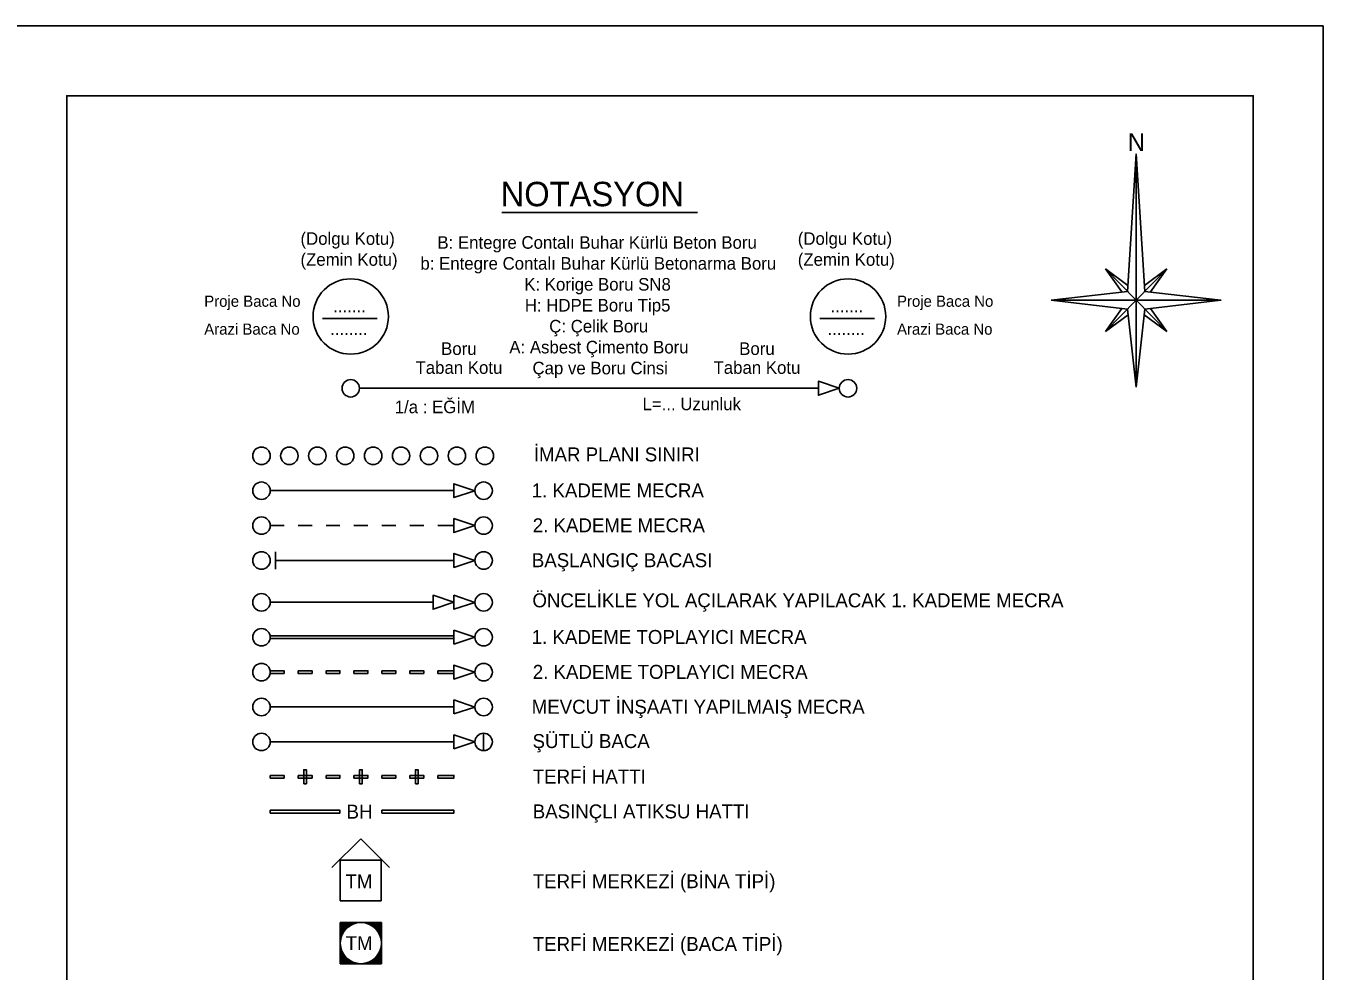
# Model space of a CAD drawing. Extents: x -10 to 821, y -10 to 550.
# Drawn here: x 635.2 to 821, y 414.6 to 550 of the extents above; entities that cross this region are included whole.
import ezdxf

# ---------------------------------------------------------------- set-up
doc = ezdxf.new("R2010")
doc.units = 0
for name, color, linetype in [('Default', 7, 'Continuous'), ('Lejand', 7, 'Continuous'), ('Level 51', 7, 'Continuous'), ('Level 52', 7, 'Continuous')]:
    doc.layers.add(name, color=color, linetype=linetype)

# ---------------------------------------------------------------- blocks, each defined once
blk = doc.blocks.new('OK')
at = {"layer": 'Default'}
blk.add_lwpolyline([(1.25, 0), (4.25, 1), (4.25, -1), (1.25, 0)], dxfattribs=at)
blk = doc.blocks.new('MENHOLE')
at = {"layer": 'Default'}
blk.add_circle((0, 0), 1.25, dxfattribs=at)

msp = doc.modelspace()

# ---------------------------------------------------------------- linework, layer by layer
at = {"layer": 'Lejand'}
for p, q in [((794.22, 531.67), (792.97, 511.96)), ((794.22, 531.67), (795.47, 511.96)), ((794.22, 531.67), (794.22, 498.23)), ((703.33, 523.26), (731.35, 523.26)), ((789.84, 515.17), (793.03, 512.81)), ((792.17, 511.87), (789.84, 515.17)), ((789.84, 515.17), (794.22, 510.68)), ((798.6, 515.17), (794.22, 510.68)), ((798.6, 515.17), (795.42, 512.81)), ((796.27, 511.87), (798.6, 515.17)), ((782.03, 510.68), (792.97, 511.96)), ((806.35, 510.68), (795.47, 511.96)), ((794.22, 510.68), (782.03, 510.68)), ((782.03, 510.68), (792.97, 509.4)), ((789.84, 506.19), (794.22, 510.68)), ((792.17, 509.49), (789.84, 506.19)), ((792.97, 509.4), (794.22, 498.23)), ((798.6, 506.19), (794.22, 510.68)), ((794.22, 510.68), (806.41, 510.68)), ((795.47, 509.4), (794.22, 498.23)), ((806.35, 510.68), (795.47, 509.4)), ((796.27, 509.49), (798.6, 506.19)), ((677.65, 508.07), (685.48, 508.07)), ((748.9, 508.07), (756.74, 508.07)), ((789.84, 506.19), (793.07, 508.58)), ((798.6, 506.19), (795.38, 508.58)), ((682.94, 498.07), (748.69, 498.08)), ((696.48, 483.4), (670.15, 483.4)), ((672.15, 478.4), (670.15, 478.4)), ((676.15, 478.4), (674.15, 478.4)), ((680.15, 478.4), (678.15, 478.4)), ((684.15, 478.4), (682.15, 478.4)), ((688.15, 478.4), (686.15, 478.4)), ((692.15, 478.4), (690.15, 478.4)), ((696.48, 478.4), (694.15, 478.4)), ((670.9, 474.64), (670.9, 472.14)), ((696.48, 473.4), (670.9, 473.4)), ((693.48, 467.41), (670.15, 467.41)), ((696.48, 452.4), (670.15, 452.4)), ((696.48, 447.4), (670.15, 447.4)), ((683.12, 433.5), (678.98, 429.37)), ((683.12, 433.5), (687.25, 429.37)), ((686.04, 430.45), (680.19, 430.45)), ((680.19, 430.45), (680.19, 424.6)), ((686.04, 430.45), (686.04, 424.6)), ((686.04, 424.6), (680.19, 424.6)), ((680.19, 421.5), (680.19, 415.6)), ((686.09, 421.5), (680.19, 421.5)), ((682.38, 421.4), (680.19, 421.4)), ((682.07, 421.3), (680.19, 421.3)), ((681.85, 421.2), (680.19, 421.2)), ((681.66, 421.1), (680.19, 421.1)), ((681.5, 421), (680.19, 421)), ((681.36, 420.9), (680.19, 420.9)), ((681.23, 420.8), (680.19, 420.8)), ((681.12, 420.7), (680.19, 420.7)), ((681.02, 420.6), (680.19, 420.6)), ((680.93, 420.5), (680.19, 420.5)), ((680.84, 420.4), (680.19, 420.4)), ((680.77, 420.3), (680.19, 420.3)), ((680.7, 420.2), (680.19, 420.2)), ((680.63, 420.1), (680.19, 420.1)), ((680.29, 421.5), (680.29, 419.31)), ((680.39, 421.5), (680.39, 419.62)), ((680.49, 421.5), (680.49, 419.85)), ((680.59, 421.5), (680.59, 420.03)), ((680.69, 421.5), (680.69, 420.19)), ((680.79, 421.5), (680.79, 420.33)), ((680.89, 421.5), (680.89, 420.46)), ((680.99, 421.5), (680.99, 420.57)), ((681.09, 421.5), (681.09, 420.67)), ((681.19, 421.5), (681.19, 420.76)), ((681.29, 421.5), (681.29, 420.85)), ((681.39, 421.5), (681.39, 420.93)), ((681.49, 421.5), (681.49, 421)), ((681.59, 421.5), (681.59, 421.06)), ((681.69, 421.5), (681.69, 421.12)), ((681.79, 421.5), (681.79, 421.17)), ((681.89, 421.5), (681.89, 421.22)), ((681.99, 421.5), (681.99, 421.27)), ((682.09, 421.5), (682.09, 421.31)), ((682.19, 421.5), (682.19, 421.34)), ((682.29, 421.5), (682.29, 421.38)), ((682.39, 421.5), (682.39, 421.4)), ((682.49, 421.5), (682.49, 421.43)), ((682.59, 421.5), (682.59, 421.45)), ((682.69, 421.5), (682.69, 421.47)), ((682.79, 421.5), (682.79, 421.48)), ((683.39, 421.5), (683.39, 421.49)), ((683.49, 421.5), (683.49, 421.48)), ((683.59, 421.5), (683.59, 421.47)), ((683.69, 421.5), (683.69, 421.45)), ((683.79, 421.5), (683.79, 421.43)), ((683.89, 421.5), (683.89, 421.4)), ((686.09, 421.4), (683.9, 421.4)), ((683.99, 421.5), (683.99, 421.38)), ((684.09, 421.5), (684.09, 421.34)), ((684.19, 421.5), (684.19, 421.31)), ((686.09, 421.3), (684.21, 421.3)), ((684.29, 421.5), (684.29, 421.27)), ((684.39, 421.5), (684.39, 421.22)), ((686.09, 421.2), (684.44, 421.2)), ((684.49, 421.5), (684.49, 421.17)), ((684.59, 421.5), (684.59, 421.12)), ((686.09, 421.1), (684.63, 421.1)), ((684.69, 421.5), (684.69, 421.06)), ((684.79, 421.5), (684.79, 421)), ((686.09, 421), (684.79, 421)), ((684.89, 421.5), (684.89, 420.93)), ((686.09, 420.9), (684.93, 420.9)), ((684.99, 421.5), (684.99, 420.85)), ((686.09, 420.8), (685.05, 420.8)), ((685.09, 421.5), (685.09, 420.76)), ((686.09, 420.7), (685.16, 420.7)), ((685.19, 421.5), (685.19, 420.67)), ((686.09, 420.6), (685.26, 420.6)), ((685.29, 421.5), (685.29, 420.57)), ((686.09, 420.5), (685.36, 420.5)), ((685.39, 421.5), (685.39, 420.46)), ((686.09, 420.4), (685.44, 420.4)), ((685.49, 421.5), (685.49, 420.33)), ((686.09, 420.3), (685.52, 420.3)), ((685.59, 421.5), (685.59, 420.19)), ((686.09, 420.2), (685.59, 420.2)), ((686.09, 420.1), (685.65, 420.1)), ((685.69, 421.5), (685.69, 420.03)), ((685.79, 421.5), (685.79, 419.85)), ((685.89, 421.5), (685.89, 419.62)), ((685.99, 421.5), (685.99, 419.31)), ((686.09, 421.5), (686.09, 415.6)), ((680.57, 420), (680.19, 420)), ((680.52, 419.9), (680.19, 419.9)), ((680.47, 419.8), (680.19, 419.8)), ((680.43, 419.7), (680.19, 419.7)), ((680.39, 419.6), (680.19, 419.6)), ((680.35, 419.5), (680.19, 419.5)), ((680.32, 419.4), (680.19, 419.4)), ((680.29, 419.3), (680.19, 419.3)), ((680.26, 419.2), (680.19, 419.2)), ((680.24, 419.1), (680.19, 419.1)), ((680.23, 419), (680.19, 419)), ((680.21, 418.9), (680.19, 418.9)), ((680.2, 418.8), (680.19, 418.8)), ((680.2, 418.4), (680.19, 418.4)), ((680.21, 418.2), (680.19, 418.2)), ((686.09, 420), (685.71, 420)), ((686.09, 419.9), (685.77, 419.9)), ((686.09, 419.8), (685.81, 419.8)), ((686.09, 419.7), (685.86, 419.7)), ((686.09, 419.6), (685.9, 419.6)), ((686.09, 419.5), (685.94, 419.5)), ((686.09, 419.4), (685.97, 419.4)), ((686.09, 419.3), (686, 419.3)), ((686.09, 419.2), (686.02, 419.2)), ((686.09, 419.1), (686.04, 419.1)), ((686.09, 419), (686.06, 419)), ((686.09, 418.9), (686.07, 418.9)), ((686.09, 418.2), (686.07, 418.2)), ((686.09, 418.3), (686.08, 418.3)), ((680.23, 418.1), (680.19, 418.1)), ((680.24, 418), (680.19, 418)), ((680.26, 417.9), (680.19, 417.9)), ((680.29, 417.8), (680.19, 417.8)), ((680.32, 417.7), (680.19, 417.7)), ((680.35, 417.6), (680.19, 417.6)), ((680.39, 417.5), (680.19, 417.5)), ((680.43, 417.4), (680.19, 417.4)), ((680.47, 417.3), (680.19, 417.3)), ((680.52, 417.2), (680.19, 417.2)), ((680.57, 417.1), (680.19, 417.1)), ((680.63, 417), (680.19, 417)), ((680.7, 416.9), (680.19, 416.9)), ((680.77, 416.8), (680.19, 416.8)), ((680.84, 416.7), (680.19, 416.7)), ((680.93, 416.6), (680.19, 416.6)), ((681.02, 416.5), (680.19, 416.5)), ((681.12, 416.4), (680.19, 416.4)), ((681.23, 416.3), (680.19, 416.3)), ((680.29, 417.79), (680.29, 415.6)), ((680.39, 417.48), (680.39, 415.6)), ((680.49, 417.25), (680.49, 415.6)), ((680.59, 417.07), (680.59, 415.6)), ((680.69, 416.91), (680.69, 415.6)), ((680.79, 416.77), (680.79, 415.6)), ((680.89, 416.64), (680.89, 415.6)), ((680.99, 416.53), (680.99, 415.6)), ((681.09, 416.43), (681.09, 415.6)), ((681.19, 416.34), (681.19, 415.6)), ((686.09, 416.3), (685.05, 416.3)), ((685.09, 416.34), (685.09, 415.6)), ((686.09, 416.4), (685.16, 416.4)), ((685.19, 416.43), (685.19, 415.6)), ((686.09, 416.5), (685.26, 416.5)), ((685.29, 416.53), (685.29, 415.6)), ((686.09, 416.6), (685.36, 416.6)), ((685.39, 416.64), (685.39, 415.6)), ((686.09, 416.7), (685.44, 416.7)), ((685.49, 416.77), (685.49, 415.6)), ((686.09, 416.8), (685.52, 416.8)), ((685.59, 416.91), (685.59, 415.6)), ((686.09, 416.9), (685.59, 416.9)), ((686.09, 417), (685.65, 417)), ((685.69, 417.07), (685.69, 415.6)), ((686.09, 417.1), (685.71, 417.1)), ((686.09, 417.2), (685.77, 417.2)), ((685.79, 417.25), (685.79, 415.6)), ((686.09, 417.3), (685.81, 417.3)), ((686.09, 417.4), (685.86, 417.4)), ((685.89, 417.48), (685.89, 415.6)), ((686.09, 417.5), (685.9, 417.5)), ((686.09, 417.6), (685.94, 417.6)), ((686.09, 417.7), (685.97, 417.7)), ((685.99, 417.79), (685.99, 415.6)), ((686.09, 417.8), (686, 417.8)), ((686.09, 417.9), (686.02, 417.9)), ((686.09, 418), (686.04, 418)), ((686.09, 418.1), (686.06, 418.1)), ((681.36, 416.2), (680.19, 416.2)), ((681.5, 416.1), (680.19, 416.1)), ((681.66, 416), (680.19, 416)), ((681.85, 415.9), (680.19, 415.9)), ((682.07, 415.8), (680.19, 415.8)), ((682.38, 415.7), (680.19, 415.7)), ((686.09, 415.6), (680.19, 415.6)), ((681.29, 416.25), (681.29, 415.6)), ((681.39, 416.18), (681.39, 415.6)), ((681.49, 416.1), (681.49, 415.6)), ((681.59, 416.04), (681.59, 415.6)), ((681.69, 415.98), (681.69, 415.6)), ((681.79, 415.93), (681.79, 415.6)), ((681.89, 415.88), (681.89, 415.6)), ((681.99, 415.83), (681.99, 415.6)), ((682.09, 415.79), (682.09, 415.6)), ((682.19, 415.76), (682.19, 415.6)), ((682.29, 415.73), (682.29, 415.6)), ((682.39, 415.7), (682.39, 415.6)), ((682.49, 415.67), (682.49, 415.6)), ((682.59, 415.65), (682.59, 415.6)), ((682.69, 415.63), (682.69, 415.6)), ((682.79, 415.62), (682.79, 415.6)), ((683.49, 415.62), (683.49, 415.6)), ((683.59, 415.63), (683.59, 415.6)), ((683.69, 415.65), (683.69, 415.6)), ((683.79, 415.67), (683.79, 415.6)), ((683.89, 415.7), (683.89, 415.6)), ((686.09, 415.7), (683.9, 415.7)), ((683.99, 415.73), (683.99, 415.6)), ((684.09, 415.76), (684.09, 415.6)), ((684.19, 415.79), (684.19, 415.6)), ((686.09, 415.8), (684.21, 415.8)), ((684.29, 415.83), (684.29, 415.6)), ((684.39, 415.88), (684.39, 415.6)), ((686.09, 415.9), (684.44, 415.9)), ((684.49, 415.93), (684.49, 415.6)), ((684.59, 415.98), (684.59, 415.6)), ((686.09, 416), (684.63, 416)), ((684.69, 416.04), (684.69, 415.6)), ((684.79, 416.1), (684.79, 415.6)), ((686.09, 416.1), (684.79, 416.1)), ((684.89, 416.18), (684.89, 415.6)), ((686.09, 416.2), (684.93, 416.2)), ((684.99, 416.25), (684.99, 415.6))]:
    msp.add_line(p, q, dxfattribs=at)
for points in [[(670.15, 462.6), (696.48, 462.6), (696.48, 462.2), (670.15, 462.2)], [(670.15, 457.6), (672.15, 457.6), (672.15, 457.2), (670.15, 457.2)], [(674.15, 457.6), (676.15, 457.6), (676.15, 457.2), (674.15, 457.2)], [(678.15, 457.6), (680.15, 457.6), (680.15, 457.2), (678.15, 457.2)], [(682.15, 457.6), (684.15, 457.6), (684.15, 457.2), (682.15, 457.2)], [(686.15, 457.6), (688.15, 457.6), (688.15, 457.2), (686.15, 457.2)], [(690.15, 457.6), (692.15, 457.6), (692.15, 457.2), (690.15, 457.2)], [(694.15, 457.6), (696.48, 457.6), (696.48, 457.2), (694.15, 457.2)], [(696.47, 451.4), (696.48, 453.4), (699.48, 452.39)], [(670.15, 442.6), (672.15, 442.6), (672.15, 442.2), (670.15, 442.2)], [(674.15, 442.6), (676.15, 442.6), (676.15, 442.2), (674.15, 442.2)], [(674.95, 441.4), (674.95, 443.4), (675.35, 443.4), (675.35, 441.4)], [(678.15, 442.6), (680.15, 442.6), (680.15, 442.2), (678.15, 442.2)], [(682.15, 442.6), (684.15, 442.6), (684.15, 442.2), (682.15, 442.2)], [(682.95, 441.4), (682.95, 443.4), (683.35, 443.4), (683.35, 441.4)], [(686.15, 442.6), (688.15, 442.6), (688.15, 442.2), (686.15, 442.2)], [(690.15, 442.6), (692.15, 442.6), (692.15, 442.2), (690.15, 442.2)], [(690.95, 441.4), (690.95, 443.4), (691.35, 443.4), (691.35, 441.4)], [(694.15, 442.6), (696.48, 442.6), (696.48, 442.2), (694.15, 442.2)], [(670.15, 437.6), (680.15, 437.6), (680.15, 437.2), (670.15, 437.2)], [(686.15, 437.6), (696.48, 437.6), (696.48, 437.2), (686.15, 437.2)]]:
    msp.add_lwpolyline(points, close=True, dxfattribs=at)
msp.add_lwpolyline([(700.73, 446.14), (700.97, 446.16), (701.21, 446.23), (701.42, 446.35), (701.61, 446.51), (701.77, 446.7), (701.88, 446.91), (701.95, 447.15), (701.98, 447.39), (701.95, 447.63), (701.88, 447.87), (701.77, 448.08), (701.61, 448.27), (701.42, 448.43), (701.21, 448.54), (700.97, 448.62), (700.73, 448.64), (700.73, 446.14)], dxfattribs=at)
for centre, radius in [((681.69, 508.36), 5.4), ((752.94, 508.36), 5.4), ((668.9, 488.39), 1.25), ((672.9, 488.39), 1.25), ((676.9, 488.39), 1.25), ((680.9, 488.39), 1.25), ((684.9, 488.39), 1.25), ((688.9, 488.39), 1.25), ((692.9, 488.39), 1.25), ((696.9, 488.39), 1.25), ((700.9, 488.39), 1.25), ((668.9, 452.39), 1.25), ((700.73, 452.39), 1.25), ((683.14, 418.55), 2.95)]:
    msp.add_circle(centre, radius, dxfattribs=at)
at = {"layer": 'Level 51'}
msp.add_lwpolyline([(-10, -10), (821, -10), (821, 550), (-10, 550)], close=True, dxfattribs=at)
at = {"layer": 'Level 52'}
msp.add_lwpolyline([(641, 287), (811, 287), (811, 540), (641, 540)], close=True, dxfattribs=at)

# ---------------------------------------------------------------- block references
at = {"layer": 'Lejand'}
for name, p, xscale, yscale, rotation in [('MENHOLE', (681.69, 498.07), 1.0000122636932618, 1.0000122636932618, 0.0008205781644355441), ('OK', (752.94, 498.07), 1.000012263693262, 1.0000122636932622, 179.87420678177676), ('MENHOLE', (752.94, 498.07), 1.0000122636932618, 1.0000122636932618, 0.0008205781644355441), ('MENHOLE', (668.9, 483.39), 1.0000122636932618, 1.0000122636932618, 0.0008205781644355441), ('OK', (700.73, 483.39), 1.000012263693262, 1.0000122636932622, 179.87420678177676), ('MENHOLE', (700.73, 483.39), 1.0000122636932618, 1.0000122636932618, 0.0008205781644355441), ('MENHOLE', (668.9, 478.39), 1.0000122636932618, 1.0000122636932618, 0.0008205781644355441), ('MENHOLE', (700.73, 478.39), 1.0000122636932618, 1.0000122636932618, 0.0008205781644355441), ('OK', (700.73, 478.39), 1.000012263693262, 1.0000122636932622, 179.87420678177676), ('MENHOLE', (668.9, 473.39), 1.0000122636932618, 1.0000122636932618, 0.0008205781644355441), ('OK', (700.73, 473.39), 1.000012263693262, 1.0000122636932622, 179.87420678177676), ('MENHOLE', (700.73, 473.39), 1.0000122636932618, 1.0000122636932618, 0.0008205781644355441), ('MENHOLE', (668.9, 467.39), 1.0000122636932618, 1.0000122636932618, 0.0008205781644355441), ('OK', (697.73, 467.4), 1.000012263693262, 1.0000122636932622, 179.87420678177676), ('OK', (700.73, 467.39), 1.000012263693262, 1.0000122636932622, 179.87420678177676), ('MENHOLE', (700.73, 467.39), 1.0000122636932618, 1.0000122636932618, 0.0008205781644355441), ('MENHOLE', (668.9, 462.39), 1.0000122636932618, 1.0000122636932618, 0.0008205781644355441), ('OK', (700.73, 462.39), 1.000012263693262, 1.0000122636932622, 179.87420678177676), ('MENHOLE', (700.73, 462.39), 1.0000122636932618, 1.0000122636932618, 0.0008205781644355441), ('MENHOLE', (668.9, 457.39), 1.0000122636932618, 1.0000122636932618, 0.0008205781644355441), ('OK', (700.73, 457.39), 1.000012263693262, 1.0000122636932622, 179.87420678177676), ('MENHOLE', (700.73, 457.39), 1.0000122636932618, 1.0000122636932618, 0.0008205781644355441), ('MENHOLE', (668.9, 447.39), 1.0000122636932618, 1.0000122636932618, 0.0008205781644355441), ('OK', (700.73, 447.39), 1.000012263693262, 1.0000122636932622, 179.87420678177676), ('MENHOLE', (700.73, 447.39), 1.0000122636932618, 1.0000122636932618, 0.0008205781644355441)]:
    msp.add_blockref(name, p, dxfattribs=dict(at, xscale=xscale, yscale=yscale, rotation=rotation))

# ---------------------------------------------------------------- texts
msp.add_text('N', height=2.56, dxfattribs=at).set_placement((793.02, 532.06))
for s, height, p in [('NOTASYON', 3.5, (703.17, 524.16)), ('(Dolgu Kotu)', 1.8, (674.49, 518.63)), ('(Dolgu Kotu)', 1.8, (745.74, 518.63)), ('B: Entegre Contalı Buhar Kürlü Beton Boru', 1.8, (694.11, 518.07)), ('(Zemin Kotu)', 1.8, (674.49, 515.63)), ('b: Entegre Contalı Buhar Kürlü Betonarma Boru', 1.8, (691.67, 515.07)), ('(Zemin Kotu)', 1.8, (745.74, 515.63)), ('K: Korige Boru SN8', 1.8, (706.55, 512.07)), ('Proje Baca No', 1.6, (660.7, 509.75)), ('Proje Baca No', 1.6, (759.96, 509.75)), ('.......', 1.8, (679.16, 508.94)), ('H: HDPE Boru Tip5', 1.8, (706.63, 509.07)), ('.......', 1.8, (750.41, 508.94)), ('Arazi Baca No', 1.6, (660.7, 505.75)), ('Ç: Çelik Boru', 1.8, (710.13, 506.07)), ('Arazi Baca No', 1.6, (759.96, 505.75)), ('........', 1.8, (678.75, 505.7)), ('........', 1.8, (750, 505.7)), ('Boru', 1.8, (694.64, 502.85)), ('A: Asbest Çimento Boru', 1.8, (704.41, 503.07)), ('Boru', 1.8, (737.35, 502.85)), ('Taban Kotu', 1.8, (690.97, 500.14)), ('Çap ve Boru Cinsi', 1.8, (707.73, 500.07)), ('Taban Kotu', 1.8, (733.67, 500.14)), ('1/a : EĞİM', 1.8, (687.99, 494.5)), ('L=... Uzunluk', 1.8, (723.49, 494.93)), ('İMAR PLANI SINIRI', 2, (707.92, 487.59)), ('1. KADEME MECRA', 2, (707.62, 482.43)), ('2. KADEME MECRA', 2, (707.77, 477.43)), ('BAŞLANGIÇ BACASI', 2, (707.64, 472.43)), ('ÖNCELİKLE YOL AÇILARAK YAPILACAK 1. KADEME MECRA', 2, (707.72, 466.68)), ('1. KADEME TOPLAYICI MECRA', 2, (707.62, 461.43)), ('2. KADEME TOPLAYICI MECRA', 2, (707.77, 456.43)), ('MEVCUT İNŞAATI YAPILMAIŞ MECRA', 2, (707.62, 451.43)), ('ŞÜTLÜ BACA', 2, (707.74, 446.51)), ('TERFİ HATTI', 2, (707.77, 441.43)), ('BH', 2, (681.09, 436.4)), ('BASINÇLI ATIKSU HATTI', 2, (707.77, 436.43)), ('TM', 2, (680.93, 426.4)), ('TERFİ MERKEZİ (BİNA TİPİ)', 2, (707.77, 426.43)), ('TM', 2, (680.96, 417.55)), ('TERFİ MERKEZİ (BACA TİPİ)', 2, (707.77, 417.43))]:
    msp.add_text(s, height=height, rotation=0.0008, dxfattribs=at).set_placement(p)

doc.saveas('drawing.dxf')
